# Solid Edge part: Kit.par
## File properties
Sűrűség: 0,000 kg/m^3
Pontosság: 0,990
Author: bmolnar
Last saved by: bmolnar
Revision: 77
Username: bmolnar
Dokumentum tartalom típus: 0
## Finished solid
Body 1: solid body, 46 faces, 63 edges, 53 vertices.
  Faces by surface: cylinder 15, cone 14, plane 12, torus 5
  Edges by curve: circle 49, line 14
Bounding box of the edges (mm; curved faces can reach further): 106.000 x 105.975 x 21.350, from (-53, -50.85, 95.1) to (53, 55.125, 116.45).
Cylindrical faces by radius (mm): R1.75 x2, R3.5 x4, R12.8 x1, R13.45 x1, R14 x1, R14.9 x1, R15 x1, R28 x1, R46.625 x1, R50.85 x1, R53 x1
Conical faces (half-angle, radius in mm at the cone's reference point): 3 deg R14.95 x1, 7 deg R14.2695 x1, 14 deg R12.65 x1, 14 deg R13.057 x1, 17 deg R12.65 x1, 23 deg R13.4211 x1, 42.5 deg R12.637 x1, 45 deg R13.7 x1, 45 deg R14.1 x1, 45 deg R27.25 x1, 60 deg R34.6072 x1, 84 deg R13.012 x1, 85 deg R14.6625 x1, 87 deg R12.7157 x1
Toroidal faces (ring radius, tube radius in mm): R13.4008 r0.225 x1, R13.8914 r0.325 x1, R14.7 r0.2 x1, R28.8 r0.8 x1, R41.2144 r0.8 x1
Planar faces by outward normal: +z 7, -z 3, oblique 2
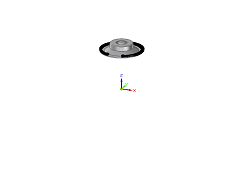
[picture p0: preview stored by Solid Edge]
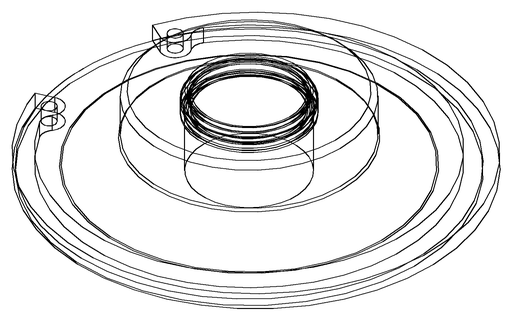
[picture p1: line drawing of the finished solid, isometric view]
